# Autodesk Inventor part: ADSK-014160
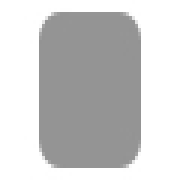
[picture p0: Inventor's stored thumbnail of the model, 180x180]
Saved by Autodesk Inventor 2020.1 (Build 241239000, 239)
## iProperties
Created: 2019-01
Part Number: ADSK-014160
Material: Stahl, weich
Document SubType Name: Modeling
Designer: lutzd
Language: de-DE
Size Designation: 5 x 39,384472 x 39,384472
Categories: <MemberInstance><Categories><Category DisplayName="Sonstige Bauteile" InternalName="5aa15e00-363f-49f2-933f-16f664388e3f" Mnemonic="OTHER"><Category DisplayName
Mass: 60.0398 g
Surface Area: 38.0412 cm^2
Volume: 7.64838 cm^3
Density: 7.85 g/cm^3
Appearance: Halbpoliert
IsCustomPart: 1
Title: end cap
Author: lutzd
Revision Number: -
Dimensions: 39,4x39,4x5 mm
Mass: 0,06 kg
DocNumber: ADSK-014160
Folder: 01 - Themengebiete\Simplification\01 - Packaging machine\
VDS_Category: 3D Komponenten
VDS_NumSchm: Autodesk
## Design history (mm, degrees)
sketch "Sketch1"
  geometry: L1 (0, 20.175)-(0, -21.446); L2 (-20.203, 0)-(20.169, 0); L3 (-19.692, 19.692)-(19.692, 19.692); L4 (19.692, 19.692)-(19.692, -19.692); L5 (19.692, -19.692)-(-19.692, -19.692); L6 (-19.692, -19.692)-(-19.692, 19.692); 1 further point
  constraints: 12 end point, 2 horizontal, 2 parallel, 2 point on line, 1 perpendicular, 1 vertical
  dimensions: "d0" = 39.38447 distance between parallel lines of L5 L3 (= height); "d1" = 19.69224 distance between parallel lines of L2 L3 (= 0.5 x height); "d2" = 39.38447 distance between parallel lines of L6 L4 (= width); "d3" = 19.69224 distance between parallel lines of L6 L1 (= 0.5 x width)
extrude "Extrusion1" new body sketch "Sketch1" distance "d4" = 5 (= thickness); taper "d5" = 0 deg
fillet "Fillet1" dims "d6" = 5 (= fillet), "d7" = 0, "fillet" = 5 [user parameter; used in 1 equation term]
chamfer "Chamfer1" distance "d8" = 0 (computed from chamfer); stored, may be unused: second distance "d9" = 2, angle "d10" = 45 deg; dims "d11" = 0, "chamfer" = 0 [user parameter; used in 1 equation term]
body "Solid1"
other parameters: "thickness" = 5 [user parameter; used in 1 equation term], "width" = 39.38447 [user parameter; used in 2 equation terms], "height" = 39.38447 [user parameter; used in 2 equation terms]
